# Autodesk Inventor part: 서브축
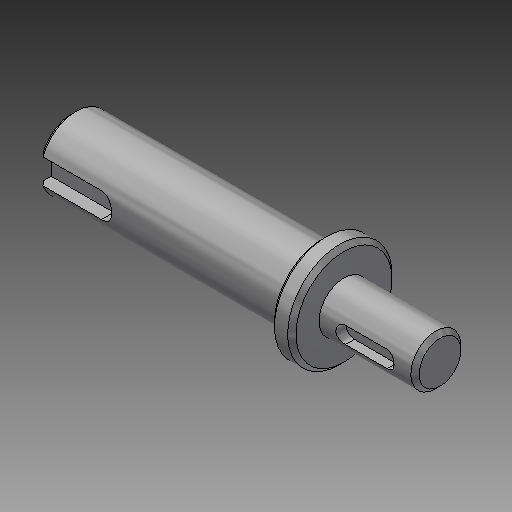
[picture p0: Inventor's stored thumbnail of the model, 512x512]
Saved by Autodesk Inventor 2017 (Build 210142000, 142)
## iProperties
Created: 2018-09
Part Number: 서브축
Document SubType Name: Modeling
Density: 7.86 g/cm^3
Material: 강철, 연강
Appearance: 강철
Mass: 142.802 g
Surface Area: 54.7946 cm^2
Volume: 18.1682 cm^3
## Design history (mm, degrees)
sketch "스케치1"
  geometry: L1 (-18.818, -7)-(-18.818, 7) reference; L2 (-41.331, -13.5)-(-41.331, 13.5) reference; L3 (-46.5, 12.249)-(-46.5, -12.249) reference; L4 (-18.331, 0)-(-106.5, 0); L5 (-18.331, 0)-(-18.331, -6); L6 (-18.331, -6)-(-41.331, -6); L7 (-41.331, -12.5)-(-46.5, -12.5); L8 (-46.5, -8.5)-(-106.5, -8.5); L9 (-106.5, -8.5)-(-106.5, 0); L10 (-46.5, -8.5)-(-46.5, -12.5); L11 (-41.331, -6)-(-41.331, -12.5); 2 further points
  constraints: 17 end point, 5 point on line, 3 parallel, 3 perpendicular, 2 collinear, 1 midpoint
  dimensions: "d0" = 23 distance between parallel lines of L2 L5; "d1" = 12 diameter of L6 L4; "d2" = 25 diameter of L7 L4; "d3" = 17 diameter of L8 L4; "d4" = 60 distance of L8.start L8.end
revolve "회전1" sketch "스케치1" stored, may be unused: angle "d5" = 90 deg
chamfer "모따기1" distance "d6" = 1; stored, may be unused: second distance "d7" = 2, angle "d8" = 45 deg
node "작업 평면1"
sketch "스케치2"
  geometry: L1 (11.5, 5)-(11.5, -5) reference; L2 (-5.5, -2)-(4.5, -2); L3 (4.5, 2)-(-5.5, 2); A1 r 2 centre (4.5, 0) between (4.5, -2) and (4.5, 2); A2 r 2 centre (-5.5, 0) between (-5.5, 2) and (-5.5, -2); 2 further points
  constraints: 4 end point, 4 point on circle, 4 tangent, 2 centre point, 1 horizontal alignment, 1 midpoint, 1 parallel, 1 perpendicular
  dimensions: "d9" = 4 distance between parallel lines of L2 L3; "d10" = 14 dimension on A1 A2; "d11" = 5 distance edge to line of A1 L1
extrude "돌출1" cut sketch "스케치2" distance "d12" = 2.5; taper "d13" = 0 deg
node "작업 평면2"
sketch "스케치3"
  geometry: L1 (-30, -7.5)-(-30, 7.5) reference; L2 (-30, 3)-(-15, 3); L3 (-15, -3)-(-30, -3); A1 r 3 centre (-15, 0) between (-15, -3) and (-15, 3); 2 further points
  constraints: 4 end point, 2 perpendicular, 2 point on circle, 2 point on line, 2 tangent, 1 centre point, 1 horizontal alignment, 1 midpoint
  dimensions: "d14" = 6 distance between parallel lines of L3 L2; "d15" = 18 dimension on A1 L1
extrude "돌출2" cut sketch "스케치3" distance "d16" = 3.5; taper "d17" = 0 deg
node "솔리드1"
node "참조1"
node "참조2"
node "참조3"
